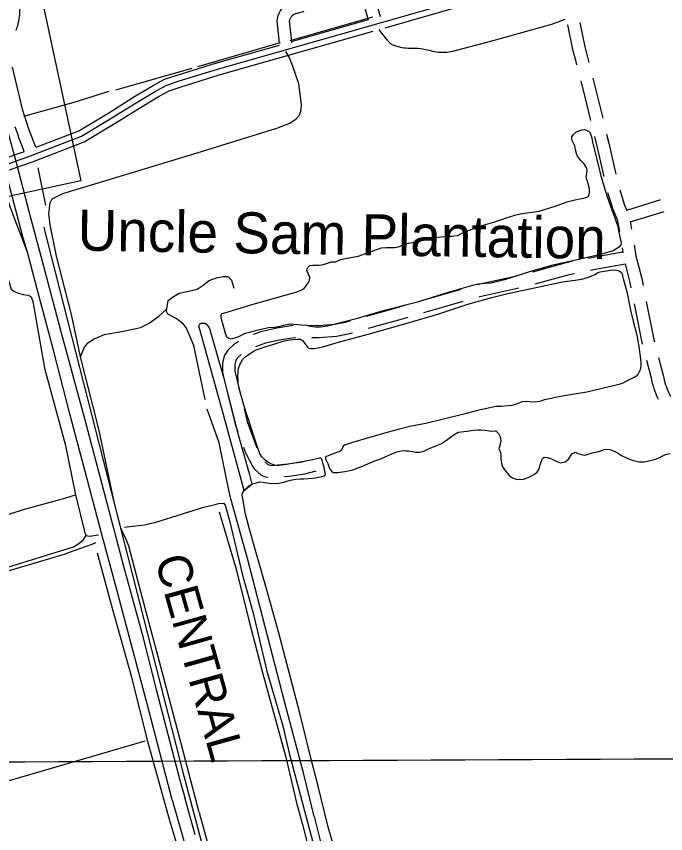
# Model space of a CAD drawing. Extents: x 3419139 to 3457078, y 540382 to 565875.
# Drawn here: x 3441333 to 3442913, y 557794 to 559786 of the extents above; entities that cross this region are included whole.
import ezdxf

# ---------------------------------------------------------------- set-up
doc = ezdxf.new("R2010")
doc.units = 0
for name, color, linetype in [('V-BLDG-IDEN', 7, 'Continuous'), ('V-DTCH-CNTR', 7, 'Continuous'), ('V-GRID-MAJR', 7, 'Continuous'), ('V-RAIL-IDEN', 7, 'Continuous'), ('V-RAIL-TRAK', 7, 'Continuous'), ('V-ROAD-CNTR', 7, 'Continuous'), ('V-SITE-OTLN', 7, 'Continuous'), ('V-TOPO-SHOR', 7, 'Continuous')]:
    doc.layers.add(name, color=color, linetype=linetype)

msp = doc.modelspace()

# ---------------------------------------------------------------- linework, layer by layer
at = {"layer": 'V-DTCH-CNTR'}
for points in [[(3441777.6, 557845.8), (3441738.7, 557995.2), (3441690.5, 558176.9), (3441639.6, 558368.3), (3441606.7, 558495), (3441600.7, 558509.5), (3441593.9, 558523.3), (3441589.8, 558531.5), (3441587.1, 558539.8), (3441570.4, 558603.2), (3441533.8, 558776.6), (3441488.9, 558956.3), (3441467, 559059.5), (3441430.1, 559201.3), (3441414.8, 559277.7), (3441411.6, 559305.9), (3441414.5, 559331.3), (3441420.1, 559341.6), (3441445.6, 559354.5), (3441558.5, 559388.1), (3441762.4, 559449.9), (3441966.9, 559513.8), (3441998.6, 559525.3), (3442013.8, 559536.2), (3442022.1, 559545), (3442025.7, 559558.8), (3442027.1, 559571.1), (3442020.6, 559621.3), (3442004.4, 559668.2), (3441997, 559686.8), (3441988.9, 559700.3)], [(3441792.6, 558852.7), (3441764.7, 558983.5), (3441746.4, 559026.2), (3441739.6, 559035.9), (3441721.8, 559049.7), (3441701.3, 559060.2), (3441697.2, 559068.5), (3441698.6, 559073.3), (3441702.2, 559093.2), (3441712.6, 559102), (3441729.1, 559111.5), (3441756, 559116.8), (3441772.5, 559121.5), (3441787.2, 559131.1), (3441802.2, 559142.4), (3441819.9, 559148.9), (3441836.1, 559152), (3441847.8, 559152.4), (3441856.5, 559143.4), (3441861.8, 559123.5)], [(3441488.9, 558956.3), (3441497.3, 558978), (3441506.6, 558990.3), (3441522, 558999.8), (3441547.3, 559010.6), (3441597.7, 559019.4), (3441634.9, 559027.9), (3441656.3, 559038.3), (3441679.7, 559055.3), (3441698.6, 559073.3)], [(3442057.8, 557836.5), (3442032.4, 557939.1), (3441985.5, 558116.7), (3441950.7, 558251.6), (3441895.1, 558465.1), (3441854.9, 558610.4), (3441850.2, 558631.7), (3441826.3, 558746.6), (3441797.3, 558828.6)], [(3441826.7, 558578.5), (3441867.7, 558438.7), (3441898.9, 558314.5), (3441932.9, 558184.2), (3441989, 557980.8), (3442015.2, 557866.1), (3442029.1, 557816.5)], [(3441777.6, 557845.8), (3441799.2, 557766.4), (3441829.9, 557631.8), (3441857.3, 557532.3), (3441888.3, 557413.2), (3441917.3, 557303.7), (3441947.7, 557190), (3441972.4, 557104.3), (3441989.3, 557063.9), (3441997.7, 557035.6), (3442003.5, 557017.4)], [(3442057.8, 557836.5), (3442081.3, 557742)], [(3442029.1, 557816.5), (3442052.9, 557724.4), (3442068.8, 557661.8)]]:
    msp.add_lwpolyline(points, dxfattribs=at)
at = {"layer": 'V-GRID-MAJR'}
msp.add_spline([(3423224.7, 557894.1), (3428498.4, 557915.2), (3433772.2, 557937), (3439045.9, 557959.6), (3444319.6, 557983), (3449593.3, 558007.2), (3454867, 558032.1)], degree=3, dxfattribs=at)
at = {"layer": 'V-RAIL-TRAK'}
for points in [[(3441711.8, 557876.8), (3441682, 557991.9), (3441651.8, 558107.5), (3441600.9, 558300.2), (3441574.1, 558400.7), (3441544.4, 558509), (3441544, 558510.8), (3441506.4, 558652.5), (3441462.9, 558817), (3441422.7, 558972.5), (3441382.5, 559124.6), (3441359.8, 559211.3), (3441347.7, 559251.9), (3441302.8, 559421.9), (3441275.3, 559523.7), (3441237.1, 559669.6), (3441197, 559828.5), (3441193, 559846.4), (3441187.1, 559883.6), (3441183.2, 559928.8)], [(3441233.6, 559749.3), (3441261.3, 559681.8), (3441281.5, 559621.2), (3441312.9, 559501.5), (3441332.4, 559429.9), (3441364.5, 559304.7), (3441395.3, 559189.1), (3441444.3, 559006), (3441498.5, 558805.8), (3441551.5, 558606.2), (3441573.4, 558523.4), (3441593.7, 558446.5), (3441637.9, 558284.1), (3441672.7, 558145.8), (3441730.3, 557924.9), (3441743.4, 557879.5)], [(3441359.8, 559211.3), (3441329.4, 559289.1), (3441315.9, 559326.3), (3441299.8, 559378.6), (3441290.4, 559417.8), (3441276.4, 559475.6), (3441238.6, 559572), (3441201.4, 559660.9)], [(3441711.8, 557876.8), (3441736.2, 557791.8), (3441761.2, 557699.8), (3441787.3, 557600.8)], [(3441767.9, 557791.5), (3441743.4, 557879.5)]]:
    msp.add_lwpolyline(points, dxfattribs=at)
at = {"layer": 'V-ROAD-CNTR'}
for p, q in [((3442201.6, 559844.7), (3442218.1, 559785.9)), ((3442173, 559835.7), (3442189.2, 559777.8))]:
    msp.add_line(p, q, dxfattribs=at)
for points in [[(3439337.9, 558886), (3439890.7, 559037.8), (3440298.7, 559149.2), (3440779.7, 559278.5), (3441232, 559408.4), (3441290.3, 559418.7), (3441333.2, 559434.1), (3441366.9, 559445.9), (3441491, 559493.6), (3441565.2, 559538.3), (3441630.8, 559579.3), (3441672.7, 559604.7), (3441699.1, 559618.6), (3441726.6, 559627.7), (3441821.9, 559657.4), (3442421.5, 559828.3), (3443074, 560013.7), (3443334.7, 560084.3), (3443393.3, 560107.2)], [(3442230.3, 559758.2), (3442425.6, 559813.9), (3442638.7, 559874.4)], [(3441331.8, 559751.5), (3441334.1, 559757.8), (3441335.8, 559763.1), (3441337.3, 559768.5), (3441338.6, 559774), (3441339.6, 559779.5), (3441340.3, 559785.1), (3441340.8, 559790.7), (3441341.1, 559796.3), (3441341.1, 559801.9), (3441340.8, 559807.5), (3441340.3, 559813.6), (3441334.8, 559839.9), (3441330.8, 559858.5)], [(3441973.1, 559719.8), (3441972.8, 559728.5), (3441967.5, 559774.8), (3441968.1, 559780), (3441968.9, 559783.8), (3441970, 559787.6), (3441971.3, 559791.3), (3441973, 559794.9), (3441974.8, 559798.3), (3441977, 559801.6), (3441979.4, 559804.7), (3441982, 559807.7), (3441984.8, 559810.4), (3441987.8, 559812.9), (3441987.9, 559813)], [(3442003.1, 559721), (3442002.7, 559730.8), (3441997.7, 559774.6), (3441997.7, 559775.1), (3441998.1, 559776.7), (3441998.5, 559778.3), (3441999.1, 559779.9), (3441999.8, 559781.4), (3442000.6, 559782.9), (3442001.5, 559784.3), (3442002.6, 559785.7), (3442003.7, 559786.9), (3442004.9, 559788.1), (3442006.2, 559789.2), (3442007.6, 559790.2), (3442009, 559791.1), (3442010.5, 559791.8), (3442012.1, 559792.5), (3442013.7, 559793), (3442015.3, 559793.5), (3442018.2, 559794), (3442033.3, 559798.2)], [(3442002.6, 559724.5), (3442189.9, 559777.9)], [(3442215, 559753.8), (3442216.8, 559751.2), (3442221, 559745.4), (3442225.4, 559739.7), (3442230, 559734.2), (3442234.8, 559728.8), (3442239.7, 559723.6), (3442244.8, 559718.5), (3442249.2, 559716.6), (3442253.7, 559714.9), (3442258.3, 559713.4), (3442262.9, 559712.1), (3442267.5, 559711), (3442272.2, 559710.1), (3442277, 559709.4), (3442281.8, 559708.9), (3442286.5, 559708.6), (3442291.3, 559708.6), (3442297.6, 559708.6), (3442303.8, 559708.4), (3442310, 559708), (3442316.2, 559707.4), (3442322.3, 559706.6), (3442328.5, 559705.5), (3442334.6, 559704.2), (3442340.6, 559702.8), (3442345.5, 559701.4), (3442350.4, 559700.4), (3442355.3, 559699.5), (3442360.3, 559698.9), (3442365.4, 559698.5), (3442370.4, 559698.3), (3442375.4, 559698.4), (3442380.5, 559698.7), (3442385.5, 559699.2), (3442390.4, 559700), (3442395.4, 559701), (3442493.5, 559727), (3442636.2, 559767.2), (3442665, 559777.2), (3442668.9, 559778.9)], [(3442674.8, 559765.3), (3442687, 559705.2), (3442693.8, 559678.8), (3442696.6, 559667.8)], [(3442704.2, 559771.3), (3442716.3, 559711.9), (3442722.8, 559686.3), (3442726, 559673.8)], [(3441217, 559388.5), (3441235.4, 559393.8), (3441294.2, 559404.1), (3441338.2, 559420), (3441372.1, 559431.8), (3441497.6, 559480.1), (3441573.1, 559525.5), (3441638.7, 559566.6), (3441680.1, 559591.7), (3441705, 559604.8), (3441731.2, 559613.4), (3441826.2, 559643.1), (3442201.5, 559750)], [(3441380.7, 559467.3), (3441484.4, 559507.2), (3441557.4, 559551.1), (3441623, 559592.1), (3441665.3, 559617.8), (3441693.2, 559632.5), (3441722, 559642), (3441817.6, 559671.8), (3441973, 559716.1)], [(3441380, 559467), (3441374.3, 559481.5), (3441368.7, 559496.4), (3441363.3, 559511.4), (3441358.1, 559526.5), (3441353.1, 559541.7), (3441348.4, 559556.5), (3441323.4, 559662.3)], [(3442706.6, 559629), (3442721, 559573), (3442730.7, 559532)], [(3442736, 559635), (3442750.1, 559580.2), (3442760.1, 559538)], [(3441351.8, 559456.5), (3441346.3, 559470.8), (3441340.5, 559486.1), (3441335, 559501.5), (3441329.7, 559516.9)], [(3442740, 559493.1), (3442745.5, 559469.9), (3442762.7, 559395.7)], [(3442769.4, 559499.1), (3442774.7, 559476.8), (3442792.1, 559401.7)], [(3440887, 559324.9), (3441228.7, 559423.1), (3441286.5, 559433.2), (3441328.2, 559448.3), (3441352.6, 559456.8)], [(3442801.6, 559362.9), (3442813.4, 559326.1), (3442818.9, 559313.1)], [(3442772, 559356.8), (3442785.2, 559315.7), (3442795.6, 559291.3), (3442800.7, 559261.4)], [(3442818.6, 559313.9), (3442898.9, 559338.7), (3442901.2, 559339.3)], [(3442827.1, 559285.1), (3442907.3, 559309.9), (3442910.1, 559310.6)], [(3442826.8, 559286.6), (3442830.1, 559267.4)], [(3442836.8, 559228), (3442841.2, 559202.3), (3442855.1, 559147.2), (3442858.4, 559130.4)], [(3442809.2, 559211.4), (3442745.1, 559200.1), (3442725.5, 559196.1)], [(3442807.4, 559222), (3442809.5, 559209.7)], [(3442686.2, 559188.3), (3442667.9, 559184.6), (3442589.6, 559162.8)], [(3442815.2, 559182.5), (3442825.8, 559140.6), (3442829, 559124.4)], [(3442815.3, 559182), (3442750.7, 559170.6), (3442730.7, 559166.6)], [(3442550.8, 559152.9), (3442453.4, 559131.7), (3442453.1, 559131.6)], [(3442691.5, 559158.7), (3442674.9, 559155.4), (3442594.9, 559133.1)], [(3442556.1, 559123.4), (3442460.8, 559102.6), (3442458.4, 559101.9)], [(3442414.7, 559120.5), (3442366.7, 559106.7), (3442318.6, 559092.8)], [(3442420, 559090.8), (3442375, 559077.8), (3442323.9, 559063.1)], [(3442836.8, 559085.2), (3442855.5, 558991.5), (3442856.6, 558987.2)], [(3442866.2, 559091.2), (3442884.7, 558998.2), (3442886, 558993.2)], [(3442280.2, 559081.8), (3442254.4, 559074.4), (3442183.9, 559054.6)], [(3442145.4, 559043.8), (3442132.9, 559040.3), (3442108.2, 559035.3), (3442068.6, 559032.2), (3442046.5, 559032.9)], [(3442285.4, 559052.1), (3442262.6, 559045.5), (3442189.2, 559024.9)], [(3442006.6, 559032.5), (3441967, 559026.5), (3441930.5, 559018.1), (3441909.3, 559010.5)], [(3442150.7, 559014.1), (3442140, 559011.1), (3442112.4, 559005.5), (3442069.3, 559002.2), (3442051.8, 559002.7)], [(3441873.2, 558993.6), (3441861.2, 558985.7), (3441848.7, 558974.1), (3441839.2, 558960.2), (3441834.6, 558941.5), (3441834.5, 558917.9), (3441836.5, 558909.2)], [(3442011.8, 559002.7), (3442009.7, 559002.7), (3441972.7, 558997), (3441938.9, 558989.3), (3441914.6, 558980.5)], [(3441879.5, 558961.8), (3441871.5, 558954.4), (3441867.1, 558947.8), (3441864.6, 558937.7), (3441864.5, 558921.3), (3441874.8, 558877.7), (3441877.1, 558868.4)], [(3442866.7, 558948.5), (3442878.1, 558904.7), (3442879.3, 558898.6), (3442880.9, 558891.9), (3442882.8, 558885.4), (3442884.8, 558878.8), (3442887.1, 558872.4), (3442889.6, 558866), (3442892.3, 558859.7), (3442895.2, 558853.5), (3442895.5, 558852.9)], [(3442896.1, 558954.5), (3442907.3, 558911.4), (3442908.6, 558905.1), (3442910, 558899.5), (3442911.5, 558893.9), (3442913.3, 558888.3), (3442915.2, 558882.8), (3442917.3, 558877.4), (3442919.6, 558872.1), (3442922.1, 558866.8), (3442924.8, 558861.6), (3442926, 558859.4)], [(3441845.7, 558870.3), (3441865.9, 558789.8), (3441871.7, 558773.8)], [(3441886.8, 558829.6), (3441894.6, 558798.6), (3441917.7, 558734.7), (3441917.7, 558734.6)], [(3441885.3, 558736.2), (3441890.2, 558722.6), (3441907.4, 558689.7), (3441912.3, 558682.7), (3441928.5, 558668.1), (3441939.5, 558663.6), (3441945.6, 558662.7)], [(3441937.7, 558700.2), (3441944.7, 558693.8), (3441947.5, 558692.7), (3441953.5, 558691.8), (3441993.4, 558695.5), (3442028.5, 558700.5), (3442034.2, 558702.1)], [(3441985.4, 558664.6), (3441996.9, 558665.6), (3442034.7, 558671.1), (3442062.5, 558678.7)], [(3441452.9, 558476.9), (3441489.4, 558489.7), (3441517, 558499.8), (3441526, 558503.6)], [(3441312.8, 558435), (3441451.9, 558476.6), (3441452.9, 558476.9)]]:
    msp.add_lwpolyline(points, dxfattribs=at)
at = {"layer": 'V-SITE-OTLN'}
msp.add_lwpolyline([(3441215.1, 559326.2), (3441157, 559313.7), (3440359, 559142.1), (3440035.7, 559073.3), (3439387.2, 558935.4), (3438963.4, 560917.5), (3438901.6, 561206.6), (3440756.7, 561603.2), (3440702.2, 561858.4), (3440994.1, 561929.6), (3441319.4, 561990.3), (3441403.1, 561599), (3441739.1, 560028.5), (3441741.8, 560014.4), (3441372, 559935.4), (3441469.3, 559480.5), (3441489.7, 559384.9)], close=True, dxfattribs=at)
at = {"layer": 'V-TOPO-SHOR'}
for p, q in [((3441999.5, 559727.4), (3442200.4, 559785)), ((3441774.6, 559663.7), (3441975.4, 559722)), ((3441574.4, 559606.7), (3441760.8, 559659.6)), ((3441404.4, 559326.2), (3441385.9, 559416.6)), ((3441887.5, 558630.6), (3441905.9, 558646.2)), ((3441450.4, 558611.8), (3441476.4, 558620.3)), ((3441645.4, 558019.8), (3440845.6, 557785.6))]:
    msp.add_line(p, q, dxfattribs=at)
for points in [[(3441350.8, 559542.3), (3441473.4, 559577.2), (3441558.6, 559603.3)], [(3442444.3, 559268.3), (3442468.8, 559277), (3442497.3, 559285.5), (3442528.6, 559295.5), (3442548.7, 559302.2), (3442565.2, 559305.3), (3442605.6, 559311.6), (3442646.9, 559324.3), (3442676.4, 559334.4), (3442689.4, 559338.2), (3442704.3, 559341.5), (3442714.3, 559343.2), (3442721.2, 559345), (3442725.5, 559347.3), (3442727.4, 559351.6), (3442728.1, 559356.8), (3442728.4, 559365.5), (3442723.9, 559381.3), (3442722.1, 559385.6), (3442719.9, 559393.8), (3442721.5, 559402.7), (3442722.5, 559411.1), (3442720.3, 559418.4), (3442714.2, 559427.1), (3442707.6, 559434), (3442703.3, 559439.1), (3442699, 559445.3), (3442696.1, 559452.1), (3442694.1, 559460.6), (3442692.4, 559470.6), (3442688.6, 559478.4), (3442685.2, 559485.2), (3442685, 559492.1), (3442688, 559496.9), (3442694.7, 559503.9), (3442701.7, 559507.2), (3442710.4, 559509.2), (3442715.9, 559509.9), (3442720.4, 559508.3), (3442726.1, 559505.7), (3442729.3, 559501.8), (3442733.1, 559492.7), (3442733.5, 559489.5), (3442734.6, 559483.5)], [(3442734.6, 559483.5), (3442755.3, 559397.5), (3442771.1, 559346.3), (3442785, 559307.7), (3442796.6, 559274.1), (3442799.2, 559260.1), (3442801, 559252.8), (3442802.8, 559244.6), (3442805.4, 559235.5), (3442804.7, 559228.9), (3442799.7, 559223.7), (3442786.1, 559214.2), (3442743.9, 559203.1), (3442694.4, 559192), (3442639.1, 559179.4), (3442584.3, 559164.3), (3442521.4, 559143.7), (3442489, 559136), (3442474.6, 559135.1), (3442457.1, 559133.7), (3442443.4, 559129.9), (3442414.6, 559122.3), (3442375.8, 559110.3), (3442309.3, 559089.5), (3442225.7, 559068.7), (3442156.9, 559047.9), (3442090, 559030.8), (3442073.1, 559028.7), (3442060.4, 559028.5), (3442048.5, 559029.8), (3442039.4, 559032.3), (3442026.7, 559033.8), (3442000, 559035.6), (3441990.6, 559034.5), (3441973.7, 559029.8), (3441961.4, 559027.8), (3441946.4, 559026.6), (3441932, 559023.9), (3441911.7, 559018.8), (3441887, 559012.6), (3441873.3, 559005), (3441866.2, 559002.3), (3441855.4, 558999.6), (3441850, 559001), (3441845, 559003.8), (3441841.9, 559013.4), (3441831.6, 559051.5), (3441831.4, 559058.4), (3441832.8, 559061.6), (3441837.2, 559062.9), (3441842.7, 559064.2), (3441909.4, 559084.7), (3442013.3, 559114.1), (3442024.7, 559117.9), (3442033.6, 559122.6), (3442038.7, 559130.6), (3442044, 559137.4), (3442045.9, 559141.9), (3442046.8, 559149.2), (3442046.6, 559152.4), (3442043.5, 559158.4), (3442041.4, 559162.5), (3442040.1, 559168.2), (3442041.7, 559173), (3442047, 559178.6), (3442053.2, 559180), (3442061.6, 559179.7), (3442068.5, 559179.4), (3442076.9, 559180.3), (3442084.9, 559182.9), (3442090.2, 559184.7), (3442099.5, 559187.4), (3442104.8, 559187.8), (3442110, 559188), (3442113.7, 559189.1), (3442120.3, 559192.3), (3442125.6, 559194.1), (3442133.8, 559196.1), (3442164.4, 559201.8), (3442205.7, 559216.1), (3442221.7, 559222.1), (3442232.7, 559223), (3442242.7, 559222.9), (3442253.6, 559222.8), (3442263, 559224.4), (3442276, 559230.2), (3442287.7, 559232.9), (3442297, 559234.8), (3442307.6, 559239.3), (3442315.6, 559241.3), (3442322.6, 559241.7), (3442332, 559243.5), (3442342.9, 559245.7), (3442357.8, 559247.7), (3442374, 559249.8), (3442382.9, 559250.4), (3442392.7, 559250.6), (3442406.6, 559252.3), (3442413.5, 559255.2), (3442428.6, 559262.4), (3442444.3, 559268.3)], [(3441213.7, 559370.9), (3441237.9, 559375.2), (3441246.2, 559374.5), (3441248.9, 559369.7), (3441257.7, 559340), (3441295.9, 559200.7), (3441318.1, 559127), (3441320.2, 559121.4), (3441326.3, 559116.6), (3441336.6, 559111), (3441349, 559108.2), (3441361.4, 559106.7), (3441366.1, 559103.9), (3441368.9, 559102.5), (3441372.3, 559090.8), (3441400.7, 558928.9), (3441451.1, 558743.5)], [(3441979.9, 557035.1), (3441740.8, 557934.3), (3441409.4, 559235.8), (3441400.1, 559271.9)], [(3441985.9, 558651.8), (3441999.9, 558655.6), (3442011.8, 558658.4), (3442023.2, 558658.8), (3442032, 558658.9), (3442042, 558659.4), (3442053.4, 558660.4), (3442061.2, 558661.3), (3442069, 558663.4), (3442076.1, 558664.7), (3442082.4, 558666.6), (3442084.9, 558669.2), (3442084.3, 558674.5), (3442083.2, 558680.2), (3442082.1, 558687.8), (3442078.9, 558697.4), (3442076.8, 558703.3), (3442075.2, 558707.9), (3442073.3, 558709.8), (3442070.6, 558709.7), (3442067, 558708.2), (3442046.3, 558703.5), (3441985.7, 558692.9), (3441971.3, 558691.2), (3441965.5, 558691.3), (3441960.7, 558692.6), (3441950.6, 558696.2), (3441942.4, 558701.4), (3441936.6, 558706.3), (3441930.5, 558712.8), (3441925.1, 558719.6), (3441912.6, 558758.3), (3441886, 558838.6), (3441875.2, 558879.2), (3441872.9, 558892), (3441872.7, 558898.9), (3441871.6, 558909.4), (3441872.2, 558918.8), (3441873.7, 558927.9), (3441877.7, 558939.6), (3441883.6, 558950.2), (3441891, 558957), (3441900.1, 558963.9), (3441907.3, 558968.7), (3441916.2, 558973), (3441926.1, 558976.9), (3441939.6, 558981.4), (3441954.2, 558985.8), (3441969.3, 558990.6), (3441982.5, 558994.2), (3441994.2, 558996.5), (3442005.9, 558998.2), (3442017.9, 558999), (3442024, 558999.1), (3442029.2, 558995.7), (3442034.6, 558988.9), (3442038.9, 558983.3), (3442041.1, 558979.8), (3442043.5, 558977), (3442048, 558976.4), (3442056.7, 558976.4), (3442067.4, 558978.4), (3442077.7, 558980.5), (3442098.1, 558986.3), (3442105.8, 558988.8), (3442111.2, 558990.3), (3442117.1, 558991.8), (3442189.4, 559011.5), (3442269.2, 559034.6), (3442359.1, 559060.5), (3442431.4, 559084.8), (3442490.5, 559101), (3442529.5, 559110.8), (3442601.5, 559126.3), (3442661.9, 559139.1), (3442693.3, 559142.9), (3442708.9, 559145.7), (3442723.8, 559149.9), (3442733.3, 559153.3), (3442741.2, 559157.1), (3442747.6, 559160.8), (3442753.6, 559163.7), (3442759.2, 559164.6), (3442769.6, 559166.2), (3442779.1, 559167.7), (3442786.2, 559167.9), (3442793.6, 559167.6), (3442797.8, 559166.6), (3442802.5, 559164.6), (3442805.6, 559162), (3442807.4, 559158.5), (3442808.1, 559154.6), (3442808.7, 559152.1), (3442808.9, 559150.5), (3442810.9, 559144.2)], [(3442810.9, 559144.2), (3442818.6, 559115.3), (3442828.2, 559069.9), (3442834.5, 559043.4), (3442843.5, 559009.1), (3442848.1, 558981.6), (3442852.3, 558950.2), (3442852.6, 558940.6), (3442852.7, 558934.6), (3442852.3, 558929.5), (3442851.2, 558924.8), (3442849.9, 558921.7), (3442848.4, 558918.1), (3442846.3, 558914.6), (3442843.7, 558911.4), (3442841.6, 558909.3), (3442838.2, 558907), (3442834.3, 558904.9), (3442829.6, 558902.4), (3442823.3, 558899.6), (3442818.4, 558896.9), (3442810.7, 558892.9), (3442804.1, 558890.1), (3442799.9, 558888.5), (3442776.2, 558883), (3442721.9, 558870.2), (3442666.3, 558860.9), (3442618.8, 558851.5), (3442607.2, 558847.8), (3442593.4, 558846.1), (3442581.9, 558846.9), (3442572.4, 558847.6), (3442563.8, 558846.3), (3442557.4, 558843.9), (3442548.2, 558839.9), (3442539.2, 558837.9), (3442529.2, 558837), (3442513.9, 558835.2), (3442503.3, 558835.2), (3442500.1, 558835), (3442485.3, 558831.7), (3442455.3, 558825.2), (3442418.7, 558816.1), (3442372.5, 558804.5), (3442329.7, 558793.8), (3442290.4, 558786.3), (3442262.2, 558779.3), (3442232.2, 558770.7), (3442183.9, 558757.5), (3442140.4, 558744.1), (3442131.6, 558741.3), (3442128, 558738.8), (3442126.1, 558733.1), (3442124.2, 558729.1), (3442120, 558725.9), (3442113.2, 558723.4), (3442108.1, 558721.6), (3442102.1, 558719.2), (3442097.3, 558717.3), (3442092.1, 558715.2), (3442087.4, 558713.1), (3442085.6, 558711.8), (3442085.5, 558707.8), (3442087.8, 558702.6), (3442090.6, 558696.7), (3442092.4, 558691.7), (3442094.5, 558686.7), (3442097.6, 558681.1), (3442100.2, 558677.6), (3442103.6, 558674.2), (3442114.9, 558674.4), (3442132.5, 558677), (3442152, 558681.3), (3442171.5, 558688.3), (3442188.2, 558695.6), (3442205.5, 558702.8), (3442217.6, 558707), (3442228.5, 558711.8), (3442238.2, 558716), (3442248.4, 558720.4), (3442258.7, 558724.7), (3442269.1, 558727.2), (3442275.1, 558728.3), (3442280.3, 558727.6), (3442287, 558727), (3442296.1, 558725.7), (3442304, 558723.9), (3442315.1, 558724), (3442324.7, 558726.5), (3442337.6, 558732.7), (3442352.6, 558738.3), (3442367.3, 558745), (3442377.2, 558751.7), (3442383.4, 558756), (3442398.7, 558767.1), (3442408.2, 558772.3), (3442429.4, 558775.4), (3442445.3, 558777.4), (3442456, 558778.7), (3442464.6, 558778.7), (3442474.2, 558777.4)], [(3441887.5, 558630.6), (3441836, 558818), (3441776.5, 559031.5), (3441779.3, 559037), (3441782.7, 559038.3), (3441792.3, 559038.3), (3441798.4, 559032.8), (3441802.5, 559025.2), (3441836.6, 558906.4), (3441872, 558769.8), (3441899.4, 558671.7), (3441905.9, 558646.2)], [(3442474.2, 558777.4), (3442488.9, 558775.3), (3442498.2, 558775.6), (3442500.3, 558775.6), (3442506.2, 558769.1), (3442510.2, 558761.5), (3442512.3, 558751.9), (3442509.3, 558740.4), (3442507.1, 558732.8), (3442511.1, 558723), (3442512.2, 558716.6), (3442512.3, 558710.2), (3442512.3, 558706.6), (3442514.5, 558694), (3442516.2, 558688.3), (3442520.2, 558682.6), (3442525.1, 558675.7), (3442533, 558666), (3442540.7, 558661.1), (3442552, 558657.6), (3442567, 558658.2), (3442581.3, 558662.9), (3442592.6, 558669.2), (3442600.8, 558675.6), (3442605.7, 558683.4), (3442608.3, 558693.4), (3442612.9, 558707.2), (3442617.8, 558711.4), (3442625.4, 558711.3), (3442635.4, 558707.8), (3442645, 558702.8), (3442656.6, 558698.2), (3442668.4, 558700.2), (3442677.3, 558707.6), (3442685.4, 558719.9), (3442694.3, 558723.7), (3442700.6, 558721.1), (3442705.8, 558719), (3442710.6, 558717.5), (3442715.1, 558717), (3442719.7, 558717.7), (3442734.2, 558722.7), (3442747.5, 558724.7), (3442757.1, 558727.9), (3442766.5, 558730.9), (3442777.4, 558730.2), (3442786.2, 558727.5), (3442796.4, 558722), (3442805.8, 558715.9), (3442821.3, 558708.3), (3442834.2, 558703.8), (3442848.7, 558700.4), (3442860.8, 558700.6), (3442868.9, 558702.1), (3442889.2, 558707), (3442903.1, 558713.3), (3442912.7, 558718), (3442923.8, 558720.7)], [(3441451.1, 558743.5), (3441476.4, 558620.3), (3441498.1, 558530.7)], [(3442119.6, 557715.1), (3442091.3, 557813.7), (3442068, 557906.5), (3442050.4, 557976.1), (3442023.9, 558084.9), (3442000.2, 558175.2), (3441971.2, 558286.2), (3441941.4, 558390.6), (3441908.7, 558507.4), (3441896.8, 558548.6), (3441890.3, 558572.5), (3441882.8, 558614.9), (3441882.3, 558619.4), (3441883.4, 558624.3), (3441887.5, 558630.6), (3441892.9, 558636.6), (3441898.2, 558641.6), (3441905.9, 558646.2), (3441916.4, 558649.6), (3441925.7, 558651.4), (3441937.5, 558650), (3441952.8, 558647.6), (3441971.6, 558648.4), (3441985.9, 558651.8)], [(3440640.5, 558383.4), (3440790, 558424.6), (3440940.8, 558465.5), (3441146.7, 558522.5), (3441253.4, 558554.1), (3441355.4, 558585.7), (3441450.4, 558611.8)], [(3441595.9, 558541), (3441643.8, 558546.7), (3441670, 558552.7), (3441736.9, 558573.6), (3441789.3, 558589.8), (3441816.2, 558596.5), (3441825.1, 558599.1), (3441836.8, 558599.8), (3441840.9, 558594.9), (3441851.7, 558557.7), (3441883.1, 558424), (3441908, 558335), (3441942.1, 558190.3), (3441981.1, 558057.2), (3441996.4, 557990.4), (3442017.3, 557914.5), (3442041.4, 557822.2)], [(3441498.1, 558530.7), (3441498.5, 558529.1), (3441502.5, 558520.8), (3441510.8, 558519.6), (3441532.6, 558522.2)], [(3440683.6, 558256.8), (3440784.9, 558289.8), (3440919.1, 558326.7), (3441034.8, 558361.6), (3441173.2, 558401.2), (3441314.4, 558444.2), (3441471.5, 558493.3), (3441482.5, 558499.4), (3441495.6, 558509.7), (3441502.5, 558520.8)], [(3441529.6, 558478.9), (3441566, 558343.6), (3441611.7, 558178.8), (3441649.9, 558025.1), (3441705, 557830)], [(3441705, 557830), (3441729.1, 557748.2), (3441753.5, 557657), (3441773.6, 557568.8), (3441785, 557503.5), (3441795.8, 557458.2), (3441806.4, 557417.8), (3441822.7, 557362.4), (3441835.3, 557313.2), (3441844.9, 557263.3), (3441851.2, 557236.3), (3441862.7, 557194.3), (3441881.4, 557137.8), (3441907.9, 557039), (3441913, 557010.4), (3441917.2, 556991.9)], [(3442041.4, 557822.2), (3442065.8, 557731.1), (3442085, 557653), (3442107.6, 557576.8), (3442130.2, 557502.4), (3442150.6, 557418.9), (3442163.5, 557361.5)]]:
    msp.add_lwpolyline(points, dxfattribs=at)

# ---------------------------------------------------------------- texts
at = {"layer": 'V-BLDG-IDEN'}
msp.add_text('Uncle Sam Plantation', height=100, rotation=359.088, dxfattribs=at).set_placement((3441481.1, 559215.1))
at = {"layer": 'V-RAIL-IDEN'}
msp.add_text('CENTRAL', height=83, rotation=285.6848, dxfattribs=at).set_placement((3441669.2, 558462.6))

doc.saveas('drawing.dxf')
